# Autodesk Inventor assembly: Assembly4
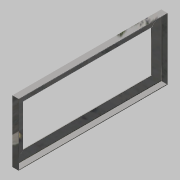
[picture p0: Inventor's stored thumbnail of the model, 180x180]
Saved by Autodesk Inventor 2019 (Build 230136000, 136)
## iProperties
Created: 2019-01
Part Number: Assembly4
Document SubType Name: Assembly
Designer: ElizabethC
_SolveAssemblyDoc: Frame Generator Solve Assembly
_Version: 15.0.0
Author: ElizabethC
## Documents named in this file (3)
- N:\CARRUTHERS\Drawings\1946556 - Hirschvogel Platform\Assembly4.iam
- N:\CARRUTHERS\Drawings\Part4.ipt
- N:\CARRUTHERS\Drawings\1946556 - Hirschvogel Platform\Assembly4\Frame\Frame0001.iam
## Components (2 placed, 2 different names)
1. Part4:1
2. Frame0001:1 [sub-assembly]
